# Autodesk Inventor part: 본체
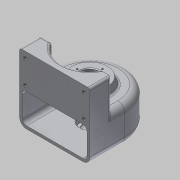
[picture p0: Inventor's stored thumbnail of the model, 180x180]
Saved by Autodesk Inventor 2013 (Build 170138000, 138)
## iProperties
Created: 2015-02
Part Number: 본체
Material: 알루미늄 6061
Document SubType Name: Modeling
Designer: Administrator
Density: 2.71 g/cm^3
Mass: 613.246 g
Surface Area: 709.081 cm^2
Volume: 226.29 cm^3
Author: Administrator
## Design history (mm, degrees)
sketch "스케치1"
  geometry: L1 (-50, -50)-(50, -50); L2 (-50, 0)-(-50, -50); L3 (50, 0)-(50, -50); A1 r 50 centre (0, 0) between (50, 0) and (-50, 0); 1 further point
  constraints: 6 end point, 2 point on circle, 2 tangent, 1 centre point, 1 coincident, 1 horizontal, 1 parallel, 1 perpendicular
  dimensions: "d0" = 100 diameter of A1; "d2" = 50 distance from line of L1 point (0, 0)
extrude "돌출1" new body sketch "스케치1" distance "d3" = 50; taper "d4" = 0 deg
node "작업 평면1"
feature "쉘1" dims "d9" = 4
sketch "스케치2"
  geometry: L1 (50, -20)-(-50, -20); L2 (-50, -20)-(-50, -50); L3 (-50, -50)-(50, -50); L4 (50, -50)-(50, -20); L5 (50, 0)-(50, -50) reference; L6 (50, -50)-(-50, -50) reference; L7 (-50, -50)-(-50, 0) reference; 1 further point
  constraints: 8 end point, 2 parallel, 1 horizontal, 1 perpendicular
  dimensions: "d6" = 30 distance of L1.end L2.end
extrude "돌출2" join sketch "스케치2" stored distance "d7" = 50; taper "d8" = 0 deg
sketch "스케치4"
  geometry: C1 r 40 at (0, 0); 1 further point
  constraints: 1 centre point, 1 coincident
  dimensions: "d12" = 80 diameter of C1
extrude "돌출3" cut sketch "스케치4" stored distance "d14" = 50; taper "d15" = 0 deg
sketch "스케치5"
  geometry: L1 (100, 0)-(100, 95) reference; L2 (100, 95)-(0, 95) reference; 5 further points
  constraints: 2 horizontal alignment, 2 vertical alignment
  dimensions: "d16" = 33 distance of point (91.75, 53) point (91.75, 86); "d18" = 83.5 distance of point (91.75, 86) point (8.25, 86); "d19" = 9 distance from line of point (91.75, 86) L2; "d20" = 8.25 distance from line of L1 point (91.75, 86)
hole "구멍1" sketch "스케치5" at (8.25, 86), (8.25, 53), (91.75, 86), (91.75, 53) diameter "d21" = 5.134; stored, may be unused: countersink angle "d25" = 90 deg, drill point angle "d27" = 118 deg; dims "d22" = 10, "d23" = 4, "d24" = 2, "d26" = 13
sketch "스케치8"
  geometry: C1 r 25 at (0, 0); A1 r 40 centre (0, 0) between (-34.641, -20) and (34.641, -20) reference
  constraints: 1 centre point, 1 coincident
  dimensions: "d28" = 50 diameter of C1
extrude "돌출4" join sketch "스케치8" distance "d30" = 10; taper "d31" = 0 deg
sketch "스케치9"
  geometry: C1 r 25 at (0, 0); A1 r 50 centre (0, 0) between (50, 0) and (-50, 0) reference
  constraints: 1 centre point, 1 coincident
  dimensions: "d32" = 50 diameter of C1
extrude "돌출5" join sketch "스케치9" distance "d34" = 9; taper "d35" = 0 deg
sketch "스케치10"
  geometry: L1 (0, 69.285)-(0, -69.285); L2 (25, 60)-(-25, 60) reference; L3 (-25, -9)-(25, -9) reference; L4 (0, 60)-(14, 60); L5 (14, 60)-(14, 50); L6 (14, 50)-(10, 50); L7 (10, 50)-(10, 4); L8 (10, 4)-(14, 4); L9 (14, 4)-(14, -4); L10 (14, -4)-(10, -4); L11 (10, -4)-(10, -6); L12 (10, -6)-(0, -6); L13 (46, 4)-(0, 4) reference; L14 (0, 60)-(0, -6); 2 further points
  constraints: 22 end point, 4 parallel, 4 perpendicular, 3 point on line, 2 midpoint, 1 coincident, 1 collinear, 1 vertical
  dimensions: "d36" = 28 diameter of L5 L1; "d38" = 20 diameter of L7 L1; "d39" = 20 diameter of L11 L1; "d40" = 28 diameter of L9 L1; "d41" = 10 distance of L4.end L5.end; "d42" = 8 distance of L8.end L9.end; "d43" = 2 distance between parallel lines of L12 L10
revolve "회전1" sketch "스케치10" stored, may be unused: angle "d44" = 90 deg
fillet "모깎기1" dims "d45" = 10
fillet "모깎기2" dims "d46" = 0.3
fillet "모깎기3" dims "d47" = 2
fillet "모깎기4" dims "d48" = 0.3
fillet "모깎기5" dims "d49" = 3
chamfer "모따기1" distance "d50" = 1; stored, may be unused: second distance "d51" = 2, angle "d52" = 45 deg
sketch "스케치11" dims "d53" = 36
  geometry: C1 r 25 at (0, 0) reference; C2 r 15 at (0, 0) reference; 2 further points
  constraints: 2 vertical alignment, 1 coincident, 2 other
hole "구멍2" sketch "스케치11" at (0, 18) diameter "d55" = 2.459; stored, may be unused: countersink angle "d59" = 90 deg, drill point angle "d61" = 118 deg; dims "d56" = 6, "d57" = 4, "d58" = 2, "d60" = 9
node "작업 평면2"
sketch "스케치12"
  geometry: 2 further points
  constraints: 1 vertical alignment, 1 other
  dimensions: "d65" = 25 distance of point (0, 25) point (0, 0)
feature "엠보싱1" sketch "스케치12" dims "d66" = 0.5, "d67" = 0
chamfer "모따기2" distance "d69" = 1; stored, may be unused: second distance "d70" = 2, angle "d71" = 45 deg
fillet "모깎기7" dims "d72" = 6
fillet "모깎기8" dims "d73" = 3
feature "면 기울기2" dims angle "d76" = 20 deg
fillet "모깎기10" dims "d77" = 3
node "솔리드1"
pattern_circular "원형 패턴1" dims angle "d63" = 360 deg
other parameters: "d5" = -95
